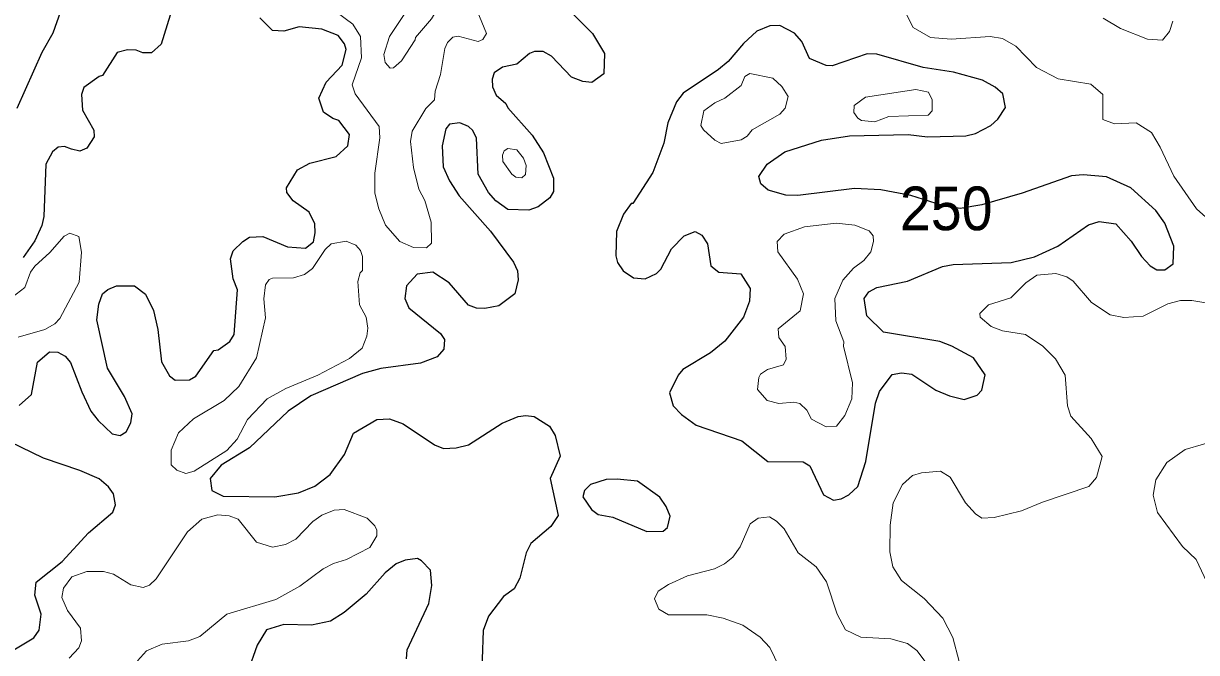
# Model space of a CAD drawing. Extents: x 763.2 to 816.8, y 7896.5 to 7952.7.
# Drawn here: x 807.081 to 811.377, y 7905.868 to 7908.172 of the extents above; entities that cross this region are included whole.
import ezdxf
from ezdxf.enums import TextEntityAlignment as Align

# ---------------------------------------------------------------- set-up
doc = ezdxf.new("R2010")
doc.units = 0
doc.header["$LTSCALE"] = 0.064
doc.layers.add('1', color=7, linetype='Continuous', lineweight=25)
doc.layers.add('2', color=7, linetype='Continuous', lineweight=13)
doc.layers.add('61', color=7, linetype='Continuous')

msp = doc.modelspace()

# ---------------------------------------------------------------- linework, layer by layer
at = {"layer": '1'}
for points in [[(807.058, 7907.8626), (807.1489, 7908.0671), (807.1888, 7908.1384), (807.2171, 7908.2169), (807.2273, 7908.2769), (807.2228, 7908.3599), (807.1915, 7908.4026), (807.1754, 7908.4148), (807.1451, 7908.4196), (807.1184, 7908.4153), (807.0848, 7908.399), (807.0508, 7908.3635)], [(808.9855, 7908.3258), (809.0508, 7908.2493), (809.1648, 7908.1354), (809.2089, 7908.062), (809.2066, 7907.9878), (809.1625, 7907.9566)], [(807.6177, 7908.2027), (807.5853, 7908.0962), (807.55, 7908.065), (807.5177, 7908.0649), (807.4929, 7908.0746), (807.4615, 7908.0761), (807.4234, 7908.0662), (807.3703, 7907.9815), (807.3576, 7907.9783), (807.3012, 7907.9374), (807.2929, 7907.9122), (807.2966, 7907.8546), (807.3382, 7907.7818), (807.3397, 7907.7574), (807.313, 7907.7155), (807.2876, 7907.7049), (807.2559, 7907.7114), (807.2309, 7907.7212), (807.2079, 7907.7197), (807.1874, 7907.7026), (807.162, 7907.6574), (807.155, 7907.465), (807.1474, 7907.4326), (807.1217, 7907.3756), (807.0793, 7907.3154)], [(808.1626, 7907.8982), (808.1894, 7907.9567), (808.2478, 7908.0195), (808.2623, 7908.0768), (808.2557, 7908.0971), (808.2329, 7908.1286), (808.1732, 7908.1519), (808.0907, 7908.1601), (808.0343, 7908.1437), (807.9927, 7908.1468), (807.9466, 7908.1924)], [(810.1363, 7906.4764), (810.1657, 7906.5676), (810.2006, 7906.782), (810.2155, 7906.8247), (810.2617, 7906.8869), (810.2965, 7906.8931), (810.3344, 7906.8872), (810.4223, 7906.829), (810.4716, 7906.8081), (810.526, 7906.7943), (810.5738, 7906.8103), (810.5903, 7906.8289), (810.6026, 7906.8855), (810.5601, 7906.9471), (810.4806, 7906.9903), (810.4364, 7907.0072), (810.2303, 7907.0418), (810.169, 7907.101), (810.1593, 7907.1643), (810.1765, 7907.1892), (810.2059, 7907.2052), (810.3177, 7907.2286), (810.4467, 7907.2815), (810.4854, 7907.2891), (810.6976, 7907.2972), (810.7837, 7907.3171), (810.8692, 7907.3565), (810.981, 7907.4352), (811.0197, 7907.4465), (811.0814, 7907.4387), (811.137, 7907.3745), (811.1745, 7907.3189), (811.2062, 7907.2843), (811.2317, 7907.2698), (811.2599, 7907.2699), (811.2908, 7907.2919), (811.293, 7907.3564), (811.2606, 7907.4412), (811.2281, 7907.4873), (811.1354, 7907.57), (811.0467, 7907.6111), (810.9612, 7907.6177), (810.9186, 7907.6144), (810.7377, 7907.5505), (810.5909, 7907.5084), (810.5111, 7907.4951), (810.4468, 7907.5061), (810.3301, 7907.5423), (810.221, 7907.5635), (810.1239, 7907.5683), (809.9168, 7907.5422), (809.872, 7907.5435), (809.8077, 7907.5621), (809.7806, 7907.5843), (809.7732, 7907.6121), (809.8038, 7907.6564), (809.8689, 7907.7017), (810.0031, 7907.7446), (810.1059, 7907.7606), (810.3206, 7907.7656), (810.3919, 7907.7575), (810.5314, 7907.7609), (810.5668, 7907.7691), (810.6232, 7907.7991), (810.6484, 7907.8212), (810.677, 7907.8649), (810.6668, 7907.9148), (810.6386, 7907.9391), (810.5924, 7907.9647), (810.4863, 7907.9937), (810.3754, 7908.0107), (810.2052, 7908.0597), (810.1708, 7908.061), (810.0425, 7908.0177), (810.0206, 7908.0179), (809.959, 7908.0437), (809.9307, 7908.1058), (809.904, 7908.1373), (809.8502, 7908.1648), (809.8142, 7908.1633), (809.7659, 7908.1447), (809.7172, 7908.0992), (809.6618, 7908.0328), (809.6261, 7908.0035), (809.497, 7907.9167), (809.4723, 7907.8848), (809.4399, 7907.8084), (809.4259, 7907.7337), (809.3854, 7907.6268), (809.3128, 7907.5132), (809.3059, 7907.5133), (809.278, 7907.4736), (809.2527, 7907.4105), (809.2505, 7907.3212), (809.2555, 7907.2965)], [(809.1625, 7907.9566), (809.1289, 7907.9602), (809.0878, 7907.9762), (809.0143, 7908.0526), (808.9842, 7908.0696), (808.9523, 7908.0693), (808.9339, 7908.0624), (808.887, 7908.0238), (808.8347, 7908.012), (808.8042, 7907.9919), (808.7969, 7907.9677), (808.7984, 7907.9399), (808.8123, 7907.9099), (808.8472, 7907.8789), (808.8547, 7907.8627), (808.944, 7907.7627), (808.9853, 7907.699), (809.0219, 7907.6055), (809.0216, 7907.5573), (809.0081, 7907.5337), (808.9654, 7907.5008), (808.9316, 7907.4879), (808.8548, 7907.491), (808.8107, 7907.5223), (808.7832, 7907.5527), (808.7462, 7907.6208), (808.7397, 7907.7518), (808.7262, 7907.7798), (808.7106, 7907.7954), (808.679, 7907.8084), (808.6408, 7907.8031), (808.6277, 7907.7869), (808.6143, 7907.7239), (808.6179, 7907.6476), (808.6411, 7907.5958), (808.6756, 7907.5405), (808.7907, 7907.4118), (808.8753, 7907.2979), (808.8902, 7907.266), (808.8918, 7907.2337), (808.88, 7907.1818), (808.8214, 7907.1381), (808.7696, 7907.1282), (808.7394, 7907.1298), (808.7105, 7907.141), (808.6401, 7907.2222), (808.5799, 7907.2611), (808.5221, 7907.254), (808.4832, 7907.2114), (808.4767, 7907.1643), (808.4917, 7907.131), (808.6083, 7907.0367), (808.6226, 7907.0141), (808.6206, 7906.9788), (808.5958, 7906.9517), (808.5348, 7906.9275), (808.3892, 7906.9081), (808.3218, 7906.8897), (808.1335, 7906.8079), (808.0503, 7906.7527), (807.9082, 7906.6174), (807.8042, 7906.5544), (807.7639, 7906.505), (807.77, 7906.461), (807.8125, 7906.4412), (808.0014, 7906.438), (808.0875, 7906.4527), (808.1476, 7906.4773), (808.2039, 7906.5205), (808.256, 7906.594), (808.2893, 7906.6711), (808.3752, 7906.722), (808.4215, 7906.7237), (808.4705, 7906.7052), (808.5858, 7906.6289), (808.6194, 7906.6153), (808.6657, 7906.6179), (808.7104, 7906.6288), (808.834, 7906.7085), (808.8921, 7906.7322), (808.9202, 7906.7368), (808.9503, 7906.7332), (809.0075, 7906.6968), (809.0279, 7906.6634), (809.0464, 7906.5878), (809.0091, 7906.5051), (809.0382, 7906.3695), (809.0125, 7906.33), (808.9387, 7906.2673), (808.9216, 7906.2332), (808.8986, 7906.1405), (808.8777, 7906.1019), (808.8387, 7906.0735), (808.7838, 7906.0006), (808.764, 7905.9481)], [(808.268, 7907.7246), (808.2742, 7907.7659), (808.2356, 7907.8173), (808.2135, 7907.8242), (808.1795, 7907.8475), (808.1626, 7907.8982)], [(807.0651, 7906.7734), (807.1098, 7906.8135), (807.1322, 7906.9318), (807.1754, 7906.9696), (807.206, 7906.9685), (807.2335, 7906.9535), (807.2532, 7906.9307), (807.2938, 7906.8225), (807.3277, 7906.7518), (807.3537, 7906.7179), (807.4056, 7906.6694), (807.4343, 7906.6633), (807.4563, 7906.6766), (807.4737, 7906.7089), (807.4786, 7906.7418), (807.45, 7906.8059), (807.3881, 7906.9101), (807.3491, 7907.0862), (807.3569, 7907.1445), (807.3695, 7907.1814), (807.3895, 7907.1982), (807.4208, 7907.2114), (807.4876, 7907.2116), (807.527, 7907.181), (807.5569, 7907.1207), (807.5724, 7907.0508), (807.5857, 7906.9325), (807.6156, 7906.8815), (807.6359, 7906.8651), (807.6892, 7906.8665), (807.7119, 7906.8798), (807.7775, 7906.9744), (807.7934, 7906.9769), (807.8358, 7907.0071), (807.8524, 7907.0324), (807.8648, 7907.1964), (807.8487, 7907.2372), (807.8387, 7907.3103), (807.8491, 7907.3389), (807.8842, 7907.3742), (807.9078, 7907.3891), (807.9569, 7907.3924), (808.0477, 7907.3547), (808.1139, 7907.3496), (808.1427, 7907.3722), (808.1492, 7907.4055), (808.1475, 7907.4386), (808.1272, 7907.4812), (808.0683, 7907.5231), (808.0448, 7907.5532), (808.0444, 7907.5701), (808.0842, 7907.636), (808.129, 7907.6603), (808.2253, 7907.6855), (808.268, 7907.7246)], [(809.4152, 7907.2728), (809.4534, 7907.3471), (809.5002, 7907.3941), (809.5406, 7907.4104), (809.5647, 7907.3971), (809.5856, 7907.3657), (809.5981, 7907.2849), (809.6275, 7907.2611), (809.7076, 7907.2555), (809.7416, 7907.2012), (809.7398, 7907.1548), (809.7171, 7907.0968), (809.6486, 7907.0086), (809.5961, 7906.9658), (809.4959, 7906.9049), (809.4777, 7906.8837), (809.4464, 7906.8193), (809.4598, 7906.7711), (809.4903, 7906.7403), (809.5441, 7906.7012), (809.7115, 7906.6434), (809.8067, 7906.5676), (809.936, 7906.567), (809.9604, 7906.5519), (810.0106, 7906.4461), (810.0465, 7906.4264), (810.0753, 7906.4306), (810.1027, 7906.4456), (810.1363, 7906.4764)], [(809.2555, 7907.2965), (809.2763, 7907.2667), (809.3146, 7907.2401), (809.3579, 7907.2369), (809.3992, 7907.256), (809.4152, 7907.2728)], [(807.0332, 7905.8701), (807.1184, 7905.9219), (807.1383, 7905.9499), (807.145, 7906.0087), (807.1223, 7906.0787), (807.1274, 7906.1253), (807.2228, 7906.2017), (807.3183, 7906.3068), (807.4079, 7906.3825), (807.4176, 7906.4088), (807.4108, 7906.4498), (807.3915, 7906.4755), (807.3575, 7906.504), (807.2865, 7906.5347), (807.1544, 7906.5795), (807.0308, 7906.6397)], [(808.483, 7905.8452), (808.4862, 7905.8774), (808.5647, 7906.0477), (808.5765, 7906.1133), (808.5716, 7906.1691), (808.5388, 7906.2039), (808.5231, 7906.2125), (808.4779, 7906.2064), (808.4455, 7906.1935), (808.4057, 7906.16), (808.335, 7906.0812), (808.255, 7906.0142), (808.2045, 7905.983), (808.1353, 7905.9679), (808.0343, 7905.9707), (807.9703, 7905.9509), (807.9361, 7905.8945), (807.9009, 7905.7943)], [(808.764, 7905.9481), (808.7568, 7905.7388), (808.7247, 7905.6775), (808.6593, 7905.6346), (808.6015, 7905.5738), (808.5348, 7905.5156)]]:
    msp.add_lwpolyline(points, dxfattribs=at)
msp.add_lwpolyline([(809.2395, 7906.3638), (809.3631, 7906.3116), (809.4228, 7906.3131), (809.4387, 7906.3257), (809.4489, 7906.3671), (809.4343, 7906.4032), (809.4112, 7906.4375), (809.3294, 7906.4958), (809.2546, 7906.5035), (809.2142, 7906.5014), (809.1575, 7906.484), (809.1356, 7906.462), (809.1292, 7906.4385), (809.1605, 7906.3916), (809.1855, 7906.3737)], close=True, dxfattribs=at)
at = {"layer": '2'}
for points in [[(808.2253, 7908.2151), (808.2863, 7908.1694), (808.3148, 7908.1242), (808.3183, 7908.0461), (808.2842, 7907.9476), (808.2958, 7907.915), (808.3831, 7907.7948), (808.3859, 7907.7538), (808.3678, 7907.6243), (808.3679, 7907.5511), (808.382, 7907.4935), (808.4067, 7907.4335), (808.4594, 7907.3736), (808.5092, 7907.3516), (808.5561, 7907.3499), (808.5747, 7907.3672), (808.5733, 7907.4445), (808.5502, 7907.5241), (808.5288, 7907.5651), (808.5088, 7907.6447), (808.4978, 7907.7403), (808.5036, 7907.7781), (808.554, 7907.8611), (808.5861, 7907.8924), (808.5887, 7907.9247), (808.6082, 7907.9856), (808.6238, 7908.0805), (808.6329, 7908.103), (808.6524, 7908.1219), (808.6721, 7908.1253), (808.7457, 7908.1062), (808.7624, 7908.1141), (808.7768, 7908.136), (808.6828, 7908.3654)], [(810.2745, 7908.2875), (810.3388, 7908.1571), (810.4025, 7908.1208), (810.4781, 7908.1142), (810.6211, 7908.124), (810.6664, 7908.1175), (810.7147, 7908.0894), (810.7903, 7908.0107), (810.8693, 7907.9695), (810.9898, 7907.9499), (811.0336, 7907.9122), (811.0338, 7907.8202), (811.0763, 7907.8052), (811.156, 7907.8083), (811.2117, 7907.773), (811.2439, 7907.7196), (811.2934, 7907.6128), (811.3762, 7907.4936), (811.4553, 7907.4227)], [(811.2896, 7908.1808), (811.2772, 7908.1433), (811.2519, 7908.1113), (811.1969, 7908.1151), (811.0983, 7908.1539), (811.0349, 7908.1921)], [(807.0606, 7907.0236), (807.1585, 7907.0507), (807.1955, 7907.0722), (807.214, 7907.092), (807.2847, 7907.2251), (807.2931, 7907.3344), (807.2831, 7907.392), (807.2502, 7907.4042), (807.2301, 7907.3936), (807.1777, 7907.3331), (807.1217, 7907.2835), (807.1059, 7907.2611), (807.0853, 7907.2052), (807.0374, 7907.1679)], [(810.992, 7907.1499), (810.9249, 7907.2282), (810.9011, 7907.2442), (810.8611, 7907.2562), (810.7913, 7907.2501), (810.7514, 7907.2221)], [(810.7514, 7907.2221), (810.6962, 7907.1669), (810.6149, 7907.1412), (810.5835, 7907.1097), (810.5838, 7907.0967), (810.6248, 7907.0621), (810.6654, 7907.0459), (810.7508, 7907.0325), (810.8133, 7906.9899), (810.8598, 7906.9435), (810.8953, 7906.884), (810.9038, 7906.7721), (810.9159, 7906.7342), (810.9908, 7906.6514), (811.0314, 7906.5855), (811.0107, 7906.5091), (810.9823, 7906.4762), (810.8127, 7906.4194), (810.7358, 7906.3874), (810.6358, 7906.3622), (810.5908, 7906.3606), (810.5675, 7906.3762), (810.5299, 7906.4169), (810.4746, 7906.51), (810.4395, 7906.5319), (810.3696, 7906.5264), (810.337, 7906.5163), (810.2993, 7906.484), (810.266, 7906.4158), (810.2546, 7906.3349), (810.2531, 7906.237), (810.2647, 7906.1824), (810.2962, 7906.1317), (810.3794, 7906.0663), (810.4477, 7905.9944), (810.4845, 7905.9234), (810.5075, 7905.8353)], [(811.4181, 7907.1478), (811.3589, 7907.1576), (811.3181, 7907.1574), (811.2712, 7907.1457), (811.1808, 7907.0999), (811.1098, 7907.0952), (811.0598, 7907.1051), (810.992, 7907.1499)], [(811.4688, 7906.6504), (811.335, 7906.6121), (811.2681, 7906.5638), (811.2272, 7906.5004), (811.2177, 7906.4446), (811.2338, 7906.381), (811.325, 7906.2567), (811.3752, 7906.2092), (811.4141, 7906.1253)], [(807.4986, 7905.8379), (807.531, 7905.8748), (807.5889, 7905.8987), (807.6852, 7905.9114), (807.7263, 7905.9265), (807.8255, 7906.0087), (808.0044, 7906.0621), (808.0922, 7906.1115), (808.1778, 7906.1751), (808.2161, 7906.1942), (808.2641, 7906.2083), (808.349, 7906.2529), (808.3742, 7906.2951), (808.3744, 7906.3168), (808.3673, 7906.3323), (808.3397, 7906.3599), (808.2554, 7906.3917), (808.2185, 7906.39), (808.1727, 7906.3712), (808.14, 7906.348), (808.0779, 7906.2829), (808.0403, 7906.2634), (807.9927, 7906.254), (807.9343, 7906.272), (807.8668, 7906.3567), (807.8335, 7906.3683), (807.7921, 7906.3719), (807.7338, 7906.3571), (807.6816, 7906.31), (807.566, 7906.1374), (807.5425, 7906.1152), (807.5191, 7906.1061), (807.4738, 7906.1157), (807.4108, 7906.1553), (807.3733, 7906.1647), (807.3122, 7906.1647), (807.2581, 7906.1448), (807.2275, 7906.1039), (807.221, 7906.0697), (807.2423, 7906.0221), (807.289, 7905.9576), (807.2931, 7905.9112), (807.2831, 7905.8857), (807.2484, 7905.8471)], [(810.458, 7905.7355), (810.3517, 7905.8753), (810.3177, 7905.9015), (810.2572, 7905.9184), (810.1471, 7905.9241), (810.0911, 7905.9509), (810.0608, 7906.0089), (810.0214, 7906.1264), (809.9838, 7906.1822), (809.9182, 7906.2334), (809.8661, 7906.3207), (809.8388, 7906.349), (809.8126, 7906.365), (809.7716, 7906.3605), (809.7421, 7906.3395), (809.7052, 7906.2548), (809.6782, 7906.2168), (809.6483, 7906.1926), (809.611, 7906.1751), (809.5118, 7906.1484), (809.4434, 7906.1175), (809.4054, 7906.0928), (809.3921, 7906.0652), (809.4069, 7906.0266), (809.4426, 7906.0066), (809.5827, 7906.0056), (809.6432, 7905.994), (809.7155, 7905.9683), (809.779, 7905.9239), (809.814, 7905.886), (809.848, 7905.8155)]]:
    msp.add_lwpolyline(points, dxfattribs=at)
for points in [[(808.5156, 7908.1128), (808.5165, 7908.121), (808.5753, 7908.1887), (808.5973, 7908.2262), (808.5943, 7908.2425), (808.5771, 7908.2623), (808.5461, 7908.2626), (808.4957, 7908.2247), (808.4866, 7908.2238), (808.4216, 7908.1243), (808.4009, 7908.0585), (808.4047, 7908.0288), (808.4234, 7908.009), (808.4355, 7908.0094), (808.4644, 7908.0352)], [(809.8501, 7907.8399), (809.8696, 7907.8626), (809.8809, 7907.9043), (809.8584, 7907.9415), (809.8243, 7907.9723), (809.7408, 7907.9892), (809.7221, 7907.9785), (809.7092, 7907.9454), (809.6497, 7907.8988), (809.6124, 7907.8815), (809.5726, 7907.852), (809.5612, 7907.7984), (809.5706, 7907.7823), (809.6125, 7907.7453), (809.6352, 7907.7331), (809.7095, 7907.7463), (809.7313, 7907.759), (809.7496, 7907.783)], [(810.3485, 7907.9299), (810.3948, 7907.9205), (810.4089, 7907.8922), (810.4089, 7907.8518), (810.394, 7907.8365), (810.2494, 7907.8314), (810.1981, 7907.8117), (810.1496, 7907.8169), (810.1359, 7907.825), (810.1216, 7907.8462), (810.1233, 7907.8723), (810.1642, 7907.9019)], [(808.8874, 7907.7089), (808.854, 7907.7147), (808.8414, 7907.7061), (808.8348, 7907.6893), (808.8363, 7907.6662), (808.8687, 7907.6201), (808.8841, 7907.6097), (808.9055, 7907.6063), (808.9187, 7907.6193), (808.9215, 7907.652), (808.9116, 7907.6785)], [(809.864, 7906.9224), (809.8732, 7906.943), (809.8696, 7906.9893), (809.8472, 7907.022), (809.8439, 7907.0535), (809.9249, 7907.1196), (809.9373, 7907.1815), (809.9152, 7907.2361), (809.8428, 7907.3354), (809.841, 7907.3735), (809.8665, 7907.4011), (809.9404, 7907.4275), (810.0573, 7907.4402), (810.1257, 7907.4337), (810.1782, 7907.4131), (810.1921, 7907.3949), (810.1937, 7907.3737), (810.1834, 7907.3362), (810.158, 7907.3045), (810.1199, 7907.2759), (810.0809, 7907.2321), (810.0525, 7907.1652), (810.0559, 7907.083), (810.0847, 7907.0063), (810.0838, 7906.9906), (810.1166, 7906.8561), (810.1146, 7906.7972), (810.0888, 7906.7364), (810.0581, 7906.6967), (810.02, 7906.6945), (809.9666, 7906.7227), (809.9489, 7906.7561), (809.9234, 7906.7797), (809.9013, 7906.7846), (809.847, 7906.7797), (809.804, 7906.7918), (809.7687, 7906.831), (809.7731, 7906.8749), (809.7799, 7906.8877), (809.8058, 7906.9051)], [(807.9668, 7907.0942), (807.9605, 7907.1637), (807.9665, 7907.2151), (807.9805, 7907.2344), (807.993, 7907.2398), (808.0693, 7907.2402), (808.1103, 7907.2522), (808.1394, 7907.2744), (808.1854, 7907.3444), (808.2078, 7907.3656), (808.2626, 7907.3744), (808.2975, 7907.3608), (808.3146, 7907.3406), (808.3218, 7907.3187), (808.3218, 7907.2671), (808.314, 7907.2593), (808.3055, 7907.2276), (808.3107, 7907.1422), (808.3352, 7907.0961), (808.3416, 7907.0564), (808.3378, 7907.0264), (808.3204, 7906.9824), (808.2742, 7906.9449), (808.1582, 7906.8835), (808.0419, 7906.835), (807.9736, 7906.7975), (807.9013, 7906.7211), (807.8634, 7906.65), (807.8248, 7906.6083), (807.7053, 7906.5323), (807.6749, 7906.5235), (807.6417, 7906.5363), (807.6216, 7906.5558), (807.6218, 7906.6096), (807.6481, 7906.6728), (807.7032, 7906.7237), (807.8151, 7906.7908), (807.8687, 7906.8427), (807.9334, 7906.9475)]]:
    msp.add_lwpolyline(points, close=True, dxfattribs=at)

# ---------------------------------------------------------------- texts
at = {"layer": '61', "width": 0.95}
msp.add_text('250', height=0.16, rotation=0.016, dxfattribs=at).set_placement((810.4599, 7907.415), align=Align.CENTER)

doc.saveas('drawing.dxf')
